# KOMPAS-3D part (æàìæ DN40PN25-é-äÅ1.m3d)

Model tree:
1. Объединить компоненты:1  (labels: СЕНС DN40PN25-В-ДП1)

Referenced files in D:\Савин\!СЕНСОР\3D для заказчика\!Новый перечень\СЕНС\5. СЕНС-В-ДП\DN40\: СЕНС DN40PN25-В-ДП1.a3d
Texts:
  СЕНС DN40PN25-В-ДП1
  ООО НПП Сенсор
